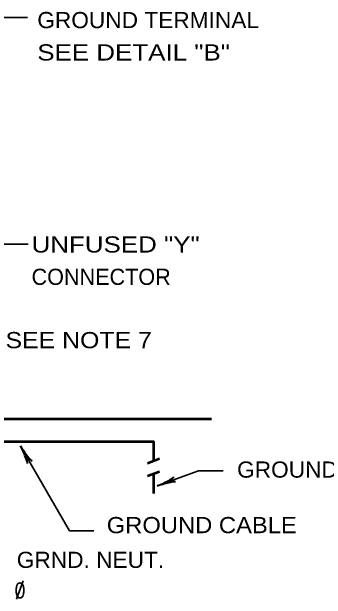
# Model space of a CAD drawing. Extents: x -217 to 639, y -295 to 249.
# Drawn here: x -19.5 to 38.9, y -219.3 to -110.3 of the extents above; entities that cross this region are included whole.
import ezdxf

# ---------------------------------------------------------------- set-up
doc = ezdxf.new("R2010")
doc.units = 0
doc.header["$LTSCALE"] = 1.2
doc.layers.add('1', color=7, linetype='Continuous', lineweight=53)

msp = doc.modelspace()

# ---------------------------------------------------------------- linework, layer by layer
at = {"layer": '1', "lineweight": 35}
for p, q in [((-16.47, -153.409), (-21.028, -153.409)), ((15.212, -195.455), (7.51, -198.259)), ((19.77, -195.455), (15.212, -195.455)), ((-17.362, -215.88), (-18.599, -219.279))]:
    msp.add_line(p, q, dxfattribs=at)
at = {"layer": '1'}
for p, q in [((-39.969, -185.804), (17.631, -185.804)), ((5.703, -194.014), (7.958, -193.193)), ((5.703, -196.414), (7.958, -195.593)), ((6.812, -196.033), (6.812, -199.633))]:
    msp.add_line(p, q, dxfattribs=at)
at = {"layer": '1', "lineweight": 35}
for points in [[(-16.575, -111.356), (-21.132, -111.356), (-35.349, -119.563)], [(-4.232, -206.572), (-8.79, -206.572), (-17.864, -190.855)]]:
    msp.add_lwpolyline(points, dxfattribs=at)
at = {"layer": '1'}
msp.add_lwpolyline([(-41.169, -130.002), (-41.169, -190.004), (6.831, -190.004), (6.831, -193.604)], dxfattribs=at)
at = {"layer": '1', "lineweight": 40}
for centre, major_axis, ratio, start_param, end_param in [((-17.412, -192.147), (-0.871, 1.931), 0.07063, 3.1407148, 5.41811), ((-16.922, -191.823), (-1.234, 1.762), 0.122415, 0.8963533, 3.1415927), ((8.627, -197.499), (-1.95, -0.909), 0.122415, 0.8963533, 3.1415927), ((8.86, -198.037), (2.053, 0.523), 0.07063, 6.2823074, 8.5597026)]:
    msp.add_ellipse(centre, major_axis=major_axis, ratio=ratio, start_param=start_param, end_param=end_param, dxfattribs=at)

# ---------------------------------------------------------------- texts
at = {"layer": '1'}
for s, width, p in [('GROUND TERMINAL', 1.05, (-14.752, -113.339)), ('SEE DETAIL "B"', 1.2, (-14.752, -119.339)), ('UNFUSED "Y"', 1.2, (-15.812, -154.964)), ('SEE NOTE 7 ', 1.15, (-20.647, -172.709)), ('GROUND ROD', 1.05, (22.363, -196.72)), ('GROUND CABLE', 1.1, (-1.85, -207.022)), ('GRND. NEUT.', 1.05, (-18.559, -213.468)), ('0', 0.9, (-18.961, -219.147))]:
    msp.add_text(s, height=3, dxfattribs=dict(at, width=width)).set_placement(p)
msp.add_text('CONNECTOR ', height=3, dxfattribs=at).set_placement((-15.812, -160.964))

doc.saveas('drawing.dxf')
